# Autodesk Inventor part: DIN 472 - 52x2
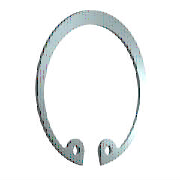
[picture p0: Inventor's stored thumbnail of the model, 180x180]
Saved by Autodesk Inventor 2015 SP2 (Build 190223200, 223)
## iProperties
Created: 2012-02
Part Number: DIN 472 - 52x2
Material: Stahl, weich
Description: Sicherungsringe für Bohrungen
Document SubType Name: Modeling
Standard: DIN 472
Designer: Dan
Standards Organization: DIN
Language: de-DE
Size Designation: 52x2
Categories: <MemberInstance><Categories><Category DisplayName="Wellenteile" InternalName="7f7aeb1f-a693-4053-b835-cee3144e0d98" Mnemonic="SHFT"><Category DisplayName="Siche
Density: 7.85 g/cm^3
Appearance: Halbpoliert
IsCustomPart: 0
Author: Dan
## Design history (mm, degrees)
node "WorkPlane1"
workplane "Work Plane2"
node "WorkPlane2"
node "WorkPoint1"
node "WorkAxis1"
body "Solid1"
node "Skizze1"
sketch "Skizze2"
  geometry: L1 (6.5, -25.487)-(5.66, -22.033); L2 (9.302, -19.786)-(11.715, -21.834); L3 (-9.302, -19.786)-(-11.715, -21.834); L4 (-6.5, -25.487)-(-5.66, -22.033); L5 (0, 1.233)-(-6.5, -25.487); L6 (0, 1.233)-(6.5, -25.487); A1 r 2.25 centre (7.846, -21.501) between (9.302, -19.786) and (5.66, -22.033); A2 r 24.778 centre (0, 0) between (11.715, -21.834) and (-11.715, -21.834); A3 r 2.25 centre (-7.846, -21.501) between (-5.66, -22.033) and (-9.302, -19.786); A4 r 27.5 centre (0, 1.233) between (6.5, -25.487) and (-6.5, -25.487); 1 further point
  constraints: 12 end point, 8 point on circle, 4 centre point, 4 tangent, 2 point on line, 1 coincident
  dimensions: "d2" = 27.5 radius of A4 (= 0.5 x Diam2); "d4" = 0 horizontal distance of A2.centre L5.start; "d6" = 24.77778 radius of A2 (= 0.5 x msp_dd1); "d8" = 1.23333 distance of A2.centre L5.start (= -0.5 x msp_dd1 + 0.5 x Diam2 - 0.222222 x ParA); "d10" = 6.5 horizontal distance of L4.start L5.start (= 2.6 x Diam5); "d12" = 6.5 horizontal distance of L1.start L5.start (= 2.6 x Diam5); "d14" = 2.25 radius of A1 (= 0.9 x Diam5); "d16" = 2.25 radius of A3 (= 0.9 x Diam5); "d18" = 24.05 distance of A3.centre L5.start (= 1.3 x Diam5 + 0.5 x Diam2 - ParA); "d20" = 24.05 distance of A1.centre L5.start (= 1.3 x Diam5 + 0.5 x Diam2 - ParA); "d22" = 36 deg angle of L1 L2; "d24" = 36 deg angle of L3 L4
extrude "Extrusion1" new body sketch "Skizze2" distance "d25" = 2 (= ParS); taper "d26" = 0 deg
sketch "Skizze3"
  geometry: A1 r 2.25 centre (-7.846, -21.501) between (-5.66, -22.033) and (-9.302, -19.786) reference; 1 further point
  constraints: 1 coincident
hole "Bohrung1" sketch "Skizze3" diameter "d29" = 2.5 (= Diam5); stored, may be unused: countersink angle "d33" = 60 deg, drill point angle "d35" = 118 deg; dims "d30" = 6, "d31" = 4, "d32" = 2, "d34" = 8
sketch "Skizze4"
  geometry: A1 r 2.25 centre (7.846, -21.501) between (9.302, -19.786) and (5.66, -22.033) reference; 1 further point
  constraints: 1 coincident
hole "Bohrung2" sketch "Skizze4" diameter "d36" = 2.5 (= Diam5); stored, may be unused: countersink angle "d40" = 60 deg, drill point angle "d42" = 118 deg; dims "d37" = 6, "d38" = 4, "d39" = 2, "d41" = 8
other parameters: "Diam5" = 2.5 [user parameter; used in 8 equation terms], "ParA" = 6.7 [user parameter; used in 4 equation terms], "b" = 4.7 [user parameter; used in 2 equation terms], "ParS" = 2 [user parameter; used in 2 equation terms], "Diam2" = 55 [user parameter; used in 6 equation terms], "msp_dd1" = 49.55556 (= -b + Diam2 - 0.111111 x ParA) [user parameter; used in 2 equation terms], "msp_pom" = 22.8 (= 0.5 x Diam2 - b) [user parameter], "d0" = -2 (computed from ParS), "d1" = 5.2 (derived), "d3" = 0 (derived), "d5" = 4.22778 (derived), "d7" = 0.28333 (derived), "d9" = 3.12 (derived), "d11" = 3.12 (derived), "d13" = 1.08 (derived), "d15" = 1.08 (derived), "d17" = 3.66 (derived), "d19" = 3.66 (derived), "d21" = 36 deg (derived), "d23" = 36 deg (derived), "d27" = 0, "d28" = 0, "d47" = 0, "d48" = 0, "d49" = 0, "d50" = 0, "TEMPLATE" = 12.345 [user parameter]
